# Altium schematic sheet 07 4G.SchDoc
size 246 x 182 mm
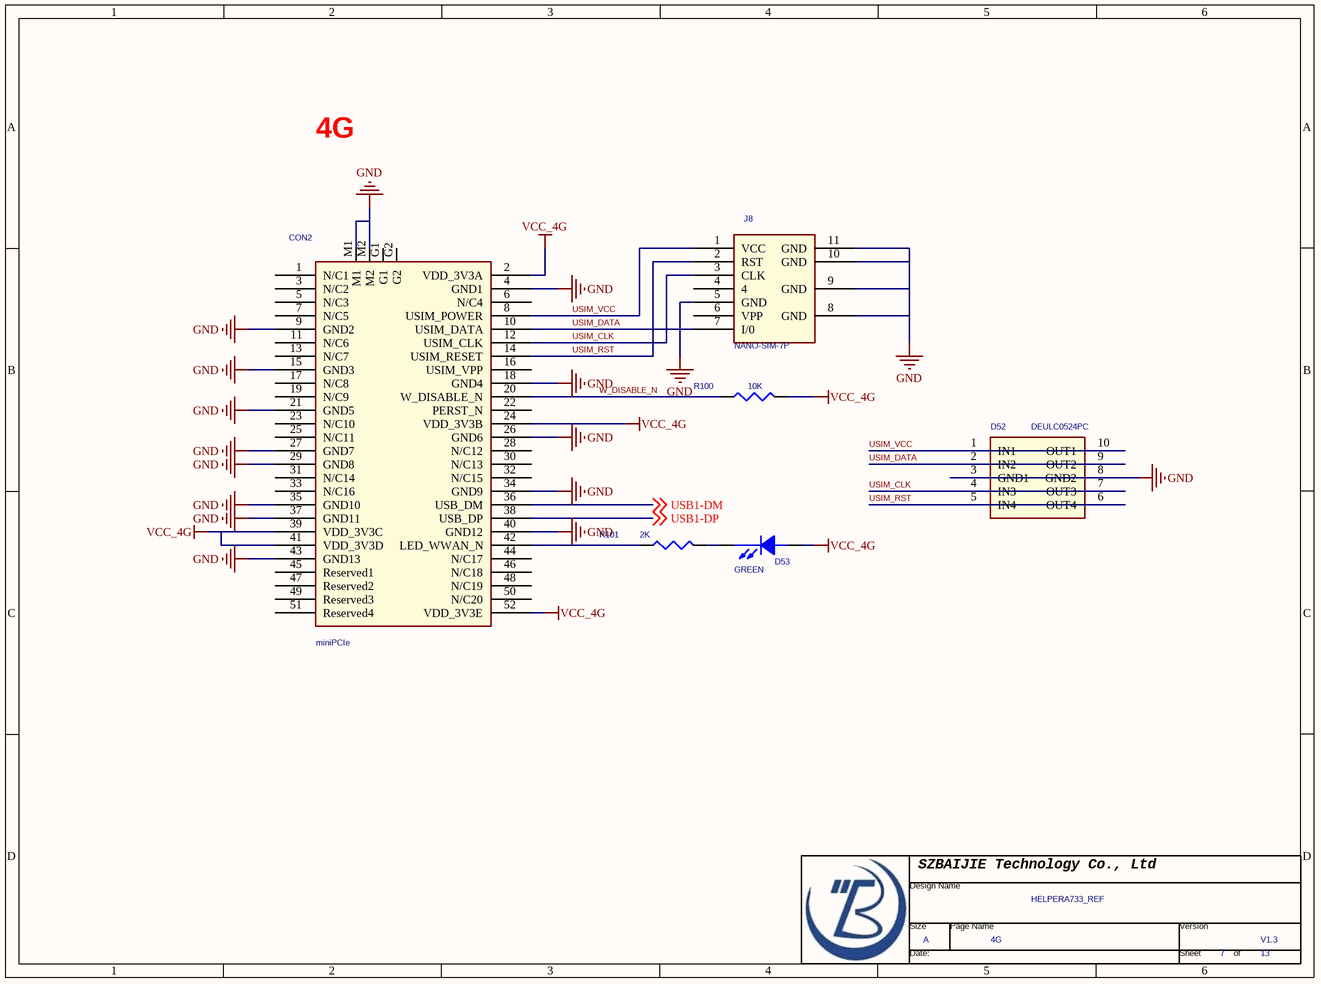
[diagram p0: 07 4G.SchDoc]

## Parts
*  Page Count: 13  Page Number: 7  Page Size: A  Title: HELPERA733_REF  RevCode: V1.3  Doc: 4G  (hidden comment: TitleBlock0-BJ)  (graphical)
CON2  miniPCIe  [MINI_PCIEX1-52P-5.2H]
D52  DEULC0524PC  [DFN2510-10_L2.5-W1.0-P0.50-BL]
D53  GREEN  [D0603]
J8  NANO-SIM-7P  [NANO-SIM-7P]
R100  10K  [R0402]
R101  2K  [R0402]

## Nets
GND: CON2.4(GND1) CON2.9(GND2) CON2.15(GND3) CON2.18(GND4) CON2.21(GND5) CON2.26(GND6) CON2.27(GND7) CON2.29(GND8) CON2.34(GND9) CON2.35(GND10) CON2.37(GND11) CON2.40(GND12) CON2.43(GND13) CON2.M1 CON2.M2 D52.3(GND1) D52.8(GND2) J8.5(GND) J8.8(GND) J8.9(GND) J8.10(GND) J8.11(GND)
VCC_4G: CON2.2(VDD_3V3A) CON2.24(VDD_3V3B) CON2.39(VDD_3V3C) CON2.41(VDD_3V3D) CON2.52(VDD_3V3E) D53.1(ANODE) R100.2
USB1-DM: CON2.36(USB_DM) ; off-sheet USB1-DM
USB1-DP: CON2.38(USB_DP) ; off-sheet USB1-DP
USIM_CLK: CON2.12(USIM_CLK) D52.4(IN3) D52.7(OUT3) J8.3(CLK)
USIM_DATA: CON2.10(USIM_DATA) D52.2(IN2) D52.9(OUT2) J8.7(I/0)
USIM_RST: CON2.14(USIM_RESET) D52.5(IN4) D52.6(OUT4) J8.2(RST)
USIM_VCC: CON2.8(USIM_POWER) D52.1(IN1) D52.10(OUT1) J8.1(VCC)
W_DISABLE_N: CON2.20(W_DISABLE_N) R100.1
NetCON2_42: CON2.42(LED_WWAN_N) R101.1
NetD53_2: D53.2(CATHODE) R101.2

Not connected (* = marked no-connect by the designer): CON2 1(N/C1) 3(N/C2) 5(N/C3) 6(N/C4) 7(N/C5) 11(N/C6) 13(N/C7) 16(USIM_VPP) 17(N/C8) 19(N/C9) 22(PERST_N) 23(N/C10) 25(N/C11) 28(N/C12) 30(N/C13) 31(N/C14) 32(N/C15) 33(N/C16) 44(N/C17) 45(Reserved1) 46(N/C18) 47(Reserved2) 48(N/C19) 49(Reserved3) 50(N/C20) 51(Reserved4) G1 G2; J8 4 6(VPP)

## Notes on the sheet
- 4G

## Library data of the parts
CON2 = CON50A_5
D52 = rRClamp0524P
D53 = LED
J8 = SIM-7P_0
R100 R101 = R_Dup5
